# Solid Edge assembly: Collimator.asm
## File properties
Author: hhakima
Template: Normal.asm
Last saved by: hhakima
Revision: 3
Application: Solid Edge
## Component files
Part - Collimator Tube.par
Part - Laser Diode.par
Part - Collimator Lens.par
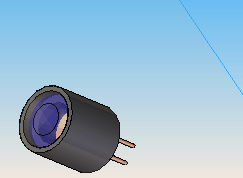
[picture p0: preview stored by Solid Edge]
